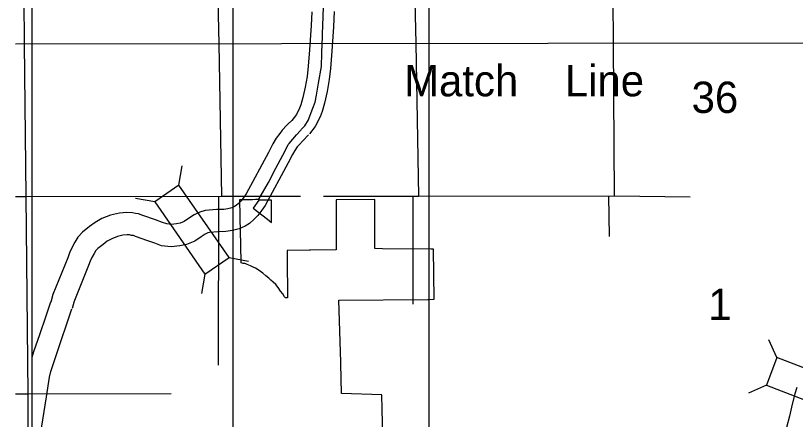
# Model space of a CAD drawing. Extents: x 1127717 to 1741049, y 2026793 to 2244711.
# Drawn here: x 1238326 to 1243581, y 2145187 to 2147909 of the extents above; entities that cross this region are included whole.
import ezdxf

# ---------------------------------------------------------------- set-up
doc = ezdxf.new("R2010")
doc.units = 0
for name, color, linetype in [('1', 7, 'Continuous'), ('10', 7, 'Continuous'), ('15', 7, 'Continuous'), ('20', 7, 'Continuous'), ('30', 7, 'Continuous'), ('4', 7, 'Continuous'), ('5', 7, 'Continuous'), ('6', 7, 'Continuous')]:
    doc.layers.add(name, color=color, linetype=linetype)

msp = doc.modelspace()

# ---------------------------------------------------------------- linework, layer by layer
at = {"layer": '1'}
msp.add_lwpolyline([(1238438.2, 2155644.2), (1269451.6, 2155644.2), (1269451.6, 2123596.1), (1238438.2, 2123596.1)], close=True, dxfattribs=at)
at = {"layer": '10'}
for points in [[(1240322.5, 2147934.2), (1240318.8, 2147842.1), (1240306.8, 2147679.3), (1240298.4, 2147567.4), (1240289.8, 2147498.8), (1240277.9, 2147425.6), (1240262, 2147356.5), (1240247.9, 2147308.2), (1240240, 2147285), (1240218.6, 2147242.8), (1240187.7, 2147202.9)], [(1240472.7, 2147935.9), (1240468.6, 2147833.5), (1240456.4, 2147668.2), (1240447.7, 2147552.4), (1240438.3, 2147477.4), (1240425.2, 2147396.7), (1240407.2, 2147318.7), (1240391, 2147263), (1240378.6, 2147226.6), (1240345.9, 2147162.2), (1240306.4, 2147111.1)], [(1240193.2, 2147209.2), (1240154.7, 2147169.5), (1240123.3, 2147136.7), (1240105.7, 2147115), (1240081.5, 2147082.2), (1240059.3, 2147043.8), (1240030.4, 2146987), (1239880.2, 2146707.5), (1239864.4, 2146684.9), (1239845.9, 2146660.6), (1239828, 2146642.9), (1239811.8, 2146628.3), (1239801.5, 2146621.9), (1239782.6, 2146613.4), (1239756.7, 2146606.9), (1239730.1, 2146602.7), (1239681.6, 2146601.4), (1239604.5, 2146595.3), (1239568.6, 2146584.5), (1239528.6, 2146566.9), (1239491.4, 2146540.9), (1239463, 2146521.2), (1239435.5, 2146510), (1239409.5, 2146505.3), (1239374.5, 2146500.6), (1239345.8, 2146504.4), (1239315.8, 2146515.1), (1239268.9, 2146532.4), (1239184.6, 2146562.4), (1239155.5, 2146572.4), (1239133.1, 2146575.4), (1239114.4, 2146579.7), (1239076.5, 2146581.6), (1239026.3, 2146577.7), (1238966.5, 2146563.7), (1238908.3, 2146540.2), (1238862.7, 2146513.6), (1238825.2, 2146486.7), (1238777.9, 2146449.6), (1238746.6, 2146415.1), (1238726.1, 2146381.7), (1238706.6, 2146347.5), (1238689.8, 2146310.3), (1238677.7, 2146277), (1238577.8, 2146029.4)], [(1240300.9, 2147104.8), (1240262.7, 2147065.3), (1240235.9, 2147037.4), (1240224.4, 2147023.3), (1240207.2, 2146999.9), (1240191.2, 2146972.2), (1240163.3, 2146917.4), (1240008.2, 2146628.8), (1239985.6, 2146596.4), (1239958.8, 2146561.3), (1239931, 2146533.8), (1239902.3, 2146508), (1239872.4, 2146489.3), (1239832.1, 2146471.2), (1239786.7, 2146459.8), (1239743.8, 2146453), (1239689.6, 2146451.6), (1239632.3, 2146447), (1239620.7, 2146443.5), (1239602.5, 2146435.5), (1239577.1, 2146417.8), (1239534.8, 2146388.4), (1239477.6, 2146365.3), (1239433, 2146357.1), (1239374.6, 2146349.2), (1239310.2, 2146357.9), (1239264.7, 2146374.1), (1239217.9, 2146391.4), (1239135.1, 2146420.8), (1239120.8, 2146425.7), (1239106.2, 2146427.7), (1239093.8, 2146430.6), (1239078.7, 2146431.3), (1239049.3, 2146429), (1239011.9, 2146420.3), (1238974.5, 2146405.2), (1238944.4, 2146387.6), (1238915.3, 2146366.7), (1238880.5, 2146339.5), (1238867.2, 2146324.7), (1238855.2, 2146305.2), (1238840.4, 2146279.3), (1238828.9, 2146253.7), (1238817.7, 2146223.3), (1238718.4, 2145976.9)], [(1238438.2, 2145606.1), (1238450.1, 2145643.5), (1238489.7, 2145759.9), (1238532.1, 2145885.8), (1238563.7, 2145980.2)], [(1238577.8, 2146029.4), (1238562.8, 2145977.2)], [(1238720.9, 2145984.1), (1238706.9, 2145935.6)], [(1238438.2, 2144844.4), (1238463.7, 2144937), (1238483.5, 2145018.4), (1238493.6, 2145086.4), (1238509.5, 2145184.9), (1238534.2, 2145338.9), (1238553.6, 2145470.6), (1238564.8, 2145509.4), (1238592.6, 2145596.6), (1238631.8, 2145711.8), (1238674.3, 2145838), (1238705.9, 2145932.6)]]:
    msp.add_lwpolyline(points, dxfattribs=at)
at = {"layer": '15'}
msp.add_lwpolyline([(1243590, 2145403), (1243576.8, 2145359.2), (1243558.3, 2145289), (1243540.2, 2145209.6), (1243519.8, 2145132.9)], dxfattribs=at)
at = {"layer": '20'}
for p, q in [((1239426.1, 2146765.8), (1239449.5, 2146895.7)), ((1239263.5, 2146652.9), (1239133.6, 2146676.3)), ((1239764.9, 2146277.9), (1239894.8, 2146254.5)), ((1239602.3, 2146165), (1239578.8, 2146035.1)), ((1243456, 2145603.2), (1243402.4, 2145723.8)), ((1243384.8, 2145418.4), (1243264.2, 2145364.8))]:
    msp.add_line(p, q, dxfattribs=at)
for points in [[(1239263.5, 2146652.9), (1239602.3, 2146165), (1239764.9, 2146277.9), (1239426.1, 2146765.8)], [(1243384.8, 2145418.4), (1243939.1, 2145205), (1244010.3, 2145389.7), (1243456, 2145603.2)]]:
    msp.add_lwpolyline(points, close=True, dxfattribs=at)
at = {"layer": '30'}
for p, q in [((1239791.2, 2119636.1), (1239791.2, 2151684.2)), ((1241111.2, 2151684.2), (1241111.2, 2119636.1)), ((1238326.3, 2147717.7), (1247968.3, 2147730.6)), ((1238326.3, 2147717.7), (1247923.9, 2147730.5))]:
    msp.add_line(p, q, dxfattribs=at)
at = {"layer": '4'}
for points in [[(1238326.3, 2146689), (1238396.7, 2146689), (1239716.3, 2146692.9), (1240245.7, 2146692.7)], [(1240400.5, 2146692.6), (1241042, 2146692.4), (1242361.7, 2146693.8), (1242871, 2146687)]]:
    msp.add_lwpolyline(points, dxfattribs=at)
at = {"layer": '5'}
for points in [[(1238369.7, 2151684.2), (1238374.3, 2150685.2), (1238369.4, 2149354), (1238381, 2148022.7), (1238384.5, 2147717.8)], [(1239697.3, 2147719.5), (1239692.1, 2148012.3), (1239693.3, 2149347.5), (1239692.7, 2150658), (1239691.9, 2151684.2)], [(1242354.3, 2147723.1), (1242352.2, 2148022.1), (1242354.5, 2149355.8), (1242345.9, 2150557.8)], [(1241023.2, 2148508.6), (1241016.9, 2148005.8), (1241022.4, 2147721.3)], [(1238384.5, 2147717.8), (1238396.2, 2146691), (1238409.8, 2145357.2), (1238408.6, 2145017.9)], [(1239715.8, 2146692.4), (1239697.3, 2147719.5)], [(1241022.4, 2147721.3), (1241042.1, 2146691.9)], [(1242361.8, 2146691.8), (1242354.3, 2147723.1)], [(1239692.8, 2145552.3), (1239694.9, 2146690.8)], [(1241003.7, 2146689.9), (1241003.6, 2145963)], [(1242329, 2146419.6), (1242324.3, 2146694.7)], [(1238326.3, 2145360.1), (1238409.3, 2145360.2), (1239374.5, 2145362.4)]]:
    msp.add_lwpolyline(points, dxfattribs=at)
at = {"layer": '6'}
for points in [[(1239923.5, 2146670.3), (1239942.5, 2146670.5), (1239946.1, 2146670.5), (1239951.4, 2146670.5), (1239964.9, 2146670.6), (1240029.6, 2146784.6), (1240059, 2146839.9), (1240059.9, 2146841.5), (1240060.9, 2146843.4), (1240061.9, 2146845.2), (1240062.8, 2146846.9), (1240063.7, 2146848.7), (1240064.7, 2146850.5), (1240142.9, 2146997.2), (1240163.8, 2147039.4), (1240165.6, 2147043.2), (1240168.5, 2147046.5), (1240218.7, 2147105.2), (1240245.6, 2147133.9), (1240249.7, 2147138.3), (1240253.8, 2147142.7), (1240262.4, 2147151.8), (1240274.9, 2147165.1), (1240300.5, 2147207.2), (1240304.9, 2147219.2), (1240329.6, 2147285.4), (1240344.8, 2147326.1), (1240353, 2147372), (1240367.3, 2147452.5), (1240387.8, 2147565.5), (1240390.6, 2147655.9), (1240390.8, 2147662.1), (1240394, 2147765.9), (1240394.7, 2147787.8), (1240396.3, 2147839.5), (1240400.2, 2147967.7)], [(1240218.7, 2147105.2), (1240245.6, 2147133.9), (1240249.7, 2147138.3), (1240253.8, 2147142.7), (1240262.4, 2147151.8), (1240274.9, 2147165.1), (1240300.5, 2147207.2), (1240304.9, 2147219.2), (1240329.6, 2147285.4), (1240344.8, 2147326.1), (1240353, 2147372), (1240367.3, 2147452.5), (1240387.8, 2147565.5), (1240390.6, 2147655.9), (1240390.8, 2147662.1), (1240394, 2147765.9), (1240394.7, 2147787.8), (1240396.3, 2147839.5), (1240400.2, 2147967.7)], [(1240801, 2145077.8), (1240796.3, 2145253.7), (1240793.7, 2145351.6), (1240523.3, 2145361.3), (1240517.3, 2145563.3), (1240517.2, 2145567.1), (1240517.1, 2145570.4), (1240517.1, 2145571.6), (1240504.6, 2145990.5), (1241104.6, 2145996.1), (1241106.1, 2145996.2), (1241107.5, 2145996.2), (1241109.1, 2145996.2), (1241110.3, 2145996.2), (1241111.9, 2145996.2), (1241146.1, 2145996.5), (1241142.4, 2146334.8), (1241126.1, 2146335), (1240798.7, 2146337.7), (1240746.7, 2146338.1), (1240746.7, 2146340.4), (1240746.7, 2146669.4), (1240485.9, 2146666.6), (1240486.9, 2146361.9), (1240487, 2146340.1), (1240487, 2146337.1), (1240487, 2146333.9), (1240487, 2146329.6), (1240486.2, 2146329.5), (1240484.7, 2146329.5), (1240312.3, 2146327.7), (1240309.1, 2146327.6), (1240306.3, 2146327.6), (1240157.1, 2146326), (1240155.7, 2146326), (1240155.7, 2146309.3), (1240155.8, 2146283.2), (1240155.8, 2146272.1), (1240158.2, 2146013.5), (1240158.2, 2146007.1), (1240144.4, 2146006.3), (1240138, 2146013.8), (1240126.2, 2146032.6), (1240110.6, 2146051.4), (1240094.8, 2146076.5), (1240079.2, 2146095.2), (1240061.1, 2146112.6), (1240046.9, 2146126.3), (1240032.7, 2146140), (1240013.3, 2146154.8), (1239991.4, 2146172.2), (1239977.2, 2146183.3), (1239961.8, 2146194.4), (1239942.5, 2146205.5), (1239927.2, 2146212.8), (1239909.2, 2146222.6), (1239897.7, 2146227.4), (1239887.5, 2146231), (1239878.5, 2146234.7), (1239870.9, 2146237.1), (1239859.4, 2146238.1), (1239845.4, 2146241.6), (1239843.2, 2146361.2), (1239843.2, 2146362.6), (1239843.1, 2146363.9), (1239839.7, 2146546.1), (1239839.7, 2146549.3), (1239839.6, 2146552.5), (1239839.6, 2146554), (1239839.5, 2146556.9), (1239839.5, 2146559.9), (1239837.5, 2146667.8), (1239836.2, 2146667.9), (1239836.2, 2146669.8), (1239914.3, 2146670.3), (1239923.5, 2146670.3), (1239923.5, 2146670.3), (1239942.5, 2146670.5), (1239946.1, 2146670.5), (1239951.4, 2146670.5), (1239964.9, 2146670.6), (1240029.6, 2146784.6), (1240059, 2146839.9), (1240059.9, 2146841.5), (1240060.9, 2146843.4), (1240061.9, 2146845.2), (1240062.8, 2146846.9), (1240063.7, 2146848.7), (1240064.7, 2146850.5), (1240142.9, 2146997.2), (1240163.8, 2147039.4), (1240165.6, 2147043.2), (1240168.5, 2147046.5), (1240218.7, 2147105.2)], [(1240801, 2145077.8), (1240796.3, 2145253.7), (1240793.7, 2145351.6), (1240523.3, 2145361.3), (1240517.3, 2145563.3), (1240517.2, 2145567.1), (1240517.1, 2145570.4), (1240517.1, 2145571.6), (1240504.6, 2145990.5), (1241104.6, 2145996.1), (1241106.1, 2145996.2), (1241107.5, 2145996.2), (1241109.1, 2145996.2), (1241110.3, 2145996.2), (1241111.9, 2145996.2), (1241146.1, 2145996.5), (1241142.4, 2146334.8), (1241126.1, 2146335), (1240798.7, 2146337.7), (1240746.7, 2146338.1), (1240746.7, 2146340.4), (1240746.7, 2146669.4), (1240485.9, 2146666.6), (1240486.9, 2146361.9), (1240487, 2146340.1), (1240487, 2146337.1), (1240487, 2146333.9), (1240487, 2146329.6), (1240486.2, 2146329.5), (1240484.7, 2146329.5), (1240312.3, 2146327.7), (1240309.1, 2146327.6), (1240306.3, 2146327.6), (1240157.1, 2146326), (1240155.7, 2146326), (1240155.7, 2146309.3), (1240155.8, 2146283.2), (1240155.8, 2146272.1), (1240158.2, 2146013.5), (1240158.2, 2146007.1), (1240144.4, 2146006.3), (1240138, 2146013.8), (1240126.2, 2146032.6), (1240110.6, 2146051.4), (1240094.8, 2146076.5), (1240079.2, 2146095.2), (1240061.1, 2146112.6), (1240046.9, 2146126.3), (1240032.7, 2146140), (1240013.3, 2146154.8), (1239991.4, 2146172.2), (1239977.2, 2146183.3), (1239961.8, 2146194.4), (1239942.5, 2146205.5), (1239927.2, 2146212.8), (1239909.2, 2146222.6), (1239897.7, 2146227.4), (1239887.5, 2146231), (1239878.5, 2146234.7), (1239870.9, 2146237.1), (1239859.4, 2146238.1), (1239845.4, 2146241.6), (1239843.2, 2146361.2), (1239843.2, 2146362.6), (1239843.1, 2146363.9), (1239839.7, 2146546.1), (1239839.7, 2146549.3), (1239839.6, 2146552.5), (1239839.6, 2146554), (1239839.5, 2146556.9), (1239839.5, 2146559.9), (1239837.5, 2146667.8), (1239836.2, 2146667.9), (1239836.2, 2146669.8), (1239914.3, 2146670.3), (1239923.5, 2146670.3), (1239923.5, 2146670.3)]]:
    msp.add_lwpolyline(points, dxfattribs=at)
msp.add_lwpolyline([(1240051.6, 2146514), (1240051.3, 2146665.1), (1239964.6, 2146664.7), (1239926.8, 2146611.2), (1240024.4, 2146536.4)], close=True, dxfattribs=at)

# ---------------------------------------------------------------- texts
at = {"layer": '30'}
msp.add_text('Match    Line', height=211.2, dxfattribs=at).set_placement((1240944, 2147364.8))
at = {"layer": '5'}
for s, p in [('36', (1242881.1, 2147252.8)), ('1', (1242993.3, 2145857.1))]:
    msp.add_text(s, height=211.2, dxfattribs=at).set_placement(p)

doc.saveas('drawing.dxf')
